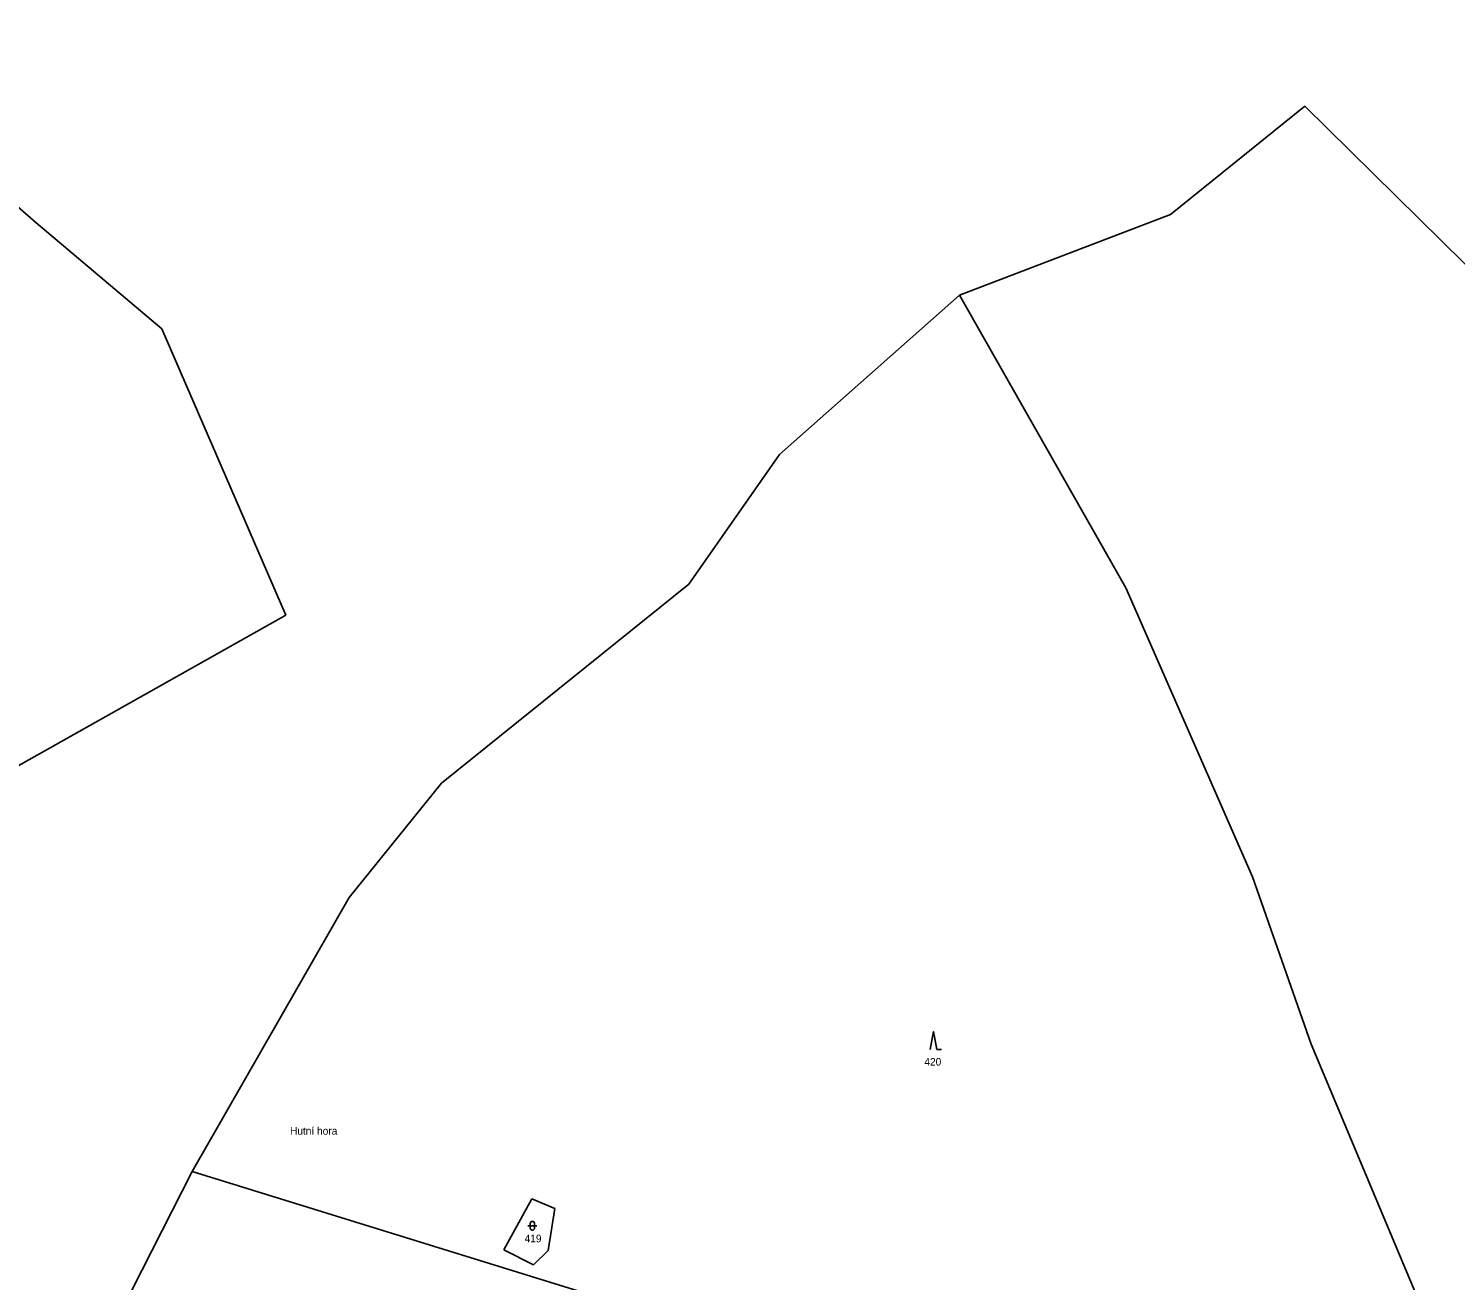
# Model space of a CAD drawing. Extents: x -670359 to -668019, y -978807 to -976674.
# Drawn here: x -668600.1 to -668280.2, y -977399.4 to -977118.7 of the extents above; entities that cross this region are included whole.
import ezdxf

# ---------------------------------------------------------------- set-up
doc = ezdxf.new("R2010")
doc.units = 0
for name, color, linetype in [('Hranice parcel', 7, 'Continuous'), ('Parcelní čísla', 7, 'Continuous'), ('Pop  PČ popisy', 7, 'Continuous'), ('Značky kultur', 7, 'Continuous')]:
    doc.layers.add(name, color=color, linetype=linetype)

msp = doc.modelspace()

# ---------------------------------------------------------------- linework, layer by layer
at = {"layer": 'Hranice parcel'}
for points in [[(-668598.5, -977162.16), (-668679.76, -977091.25)], [(-668313.99, -977136.07), (-668344.08, -977160.38)], [(-668273.05, -977176.41), (-668313.99, -977136.07)], [(-668344.08, -977160.38), (-668391.41, -977178.49)], [(-668570.19, -977186.04), (-668598.5, -977162.16)], [(-668391.41, -977178.49), (-668431.75, -977214.2)], [(-668354.08, -977244.14), (-668391.41, -977178.49)], [(-668542.42, -977250.25), (-668570.19, -977186.04)], [(-668431.75, -977214.2), (-668452.08, -977243.26)], [(-668452.08, -977243.26), (-668507.55, -977287.89)], [(-668325.7, -977308.93), (-668354.08, -977244.14)], [(-668606.65, -977286.32), (-668542.42, -977250.25)], [(-668507.55, -977287.89), (-668528.24, -977313.57)], [(-668312.52, -977346.45), (-668325.7, -977308.93)], [(-668528.24, -977313.57), (-668563.4, -977375)], [(-668302.7, -977370), (-668312.52, -977346.45)], [(-668280.24, -977423.45), (-668302.7, -977370)], [(-668563.4, -977375), (-668594.98, -977437.03)], [(-668563.4, -977375), (-668476.97, -977401.73)], [(-668493.55, -977392.58), (-668487.3, -977381.11)], [(-668487.3, -977381.11), (-668482.09, -977383.3)], [(-668482.09, -977383.3), (-668483.62, -977392.69)], [(-668486.86, -977395.94), (-668493.55, -977392.58)], [(-668483.62, -977392.69), (-668486.86, -977395.94)]]:
    msp.add_lwpolyline(points, dxfattribs=at)
at = {"layer": 'Značky kultur'}
for p, q in [((-668488.14, -977387.18), (-668486.14, -977387.18)), ((-668487.64, -977386.68), (-668487.64, -977387.68)), ((-668486.64, -977386.68), (-668486.64, -977387.68))]:
    msp.add_line(p, q, dxfattribs=at)
msp.add_lwpolyline([(-668397.95, -977347.64), (-668397.2, -977343.64), (-668396.45, -977347.64), (-668395.45, -977347.64)], dxfattribs=at)
for centre, start, end in [((-668487.14, -977386.68), 0, 180), ((-668487.14, -977387.68), 180, 0)]:
    msp.add_arc(centre, 0.5, start, end, dxfattribs=at)

# ---------------------------------------------------------------- texts
at = {"layer": 'Parcelní čísla'}
for s, p in [('420', (-668399.26, -977351.25)), ('419', (-668488.89, -977390.88))]:
    msp.add_text(s, height=1.7, dxfattribs=at).set_placement(p)
at = {"layer": 'Pop  PČ popisy'}
msp.add_text('Hutní hora', height=1.7, dxfattribs=at).set_placement((-668541.49, -977366.74))

doc.saveas('drawing.dxf')
